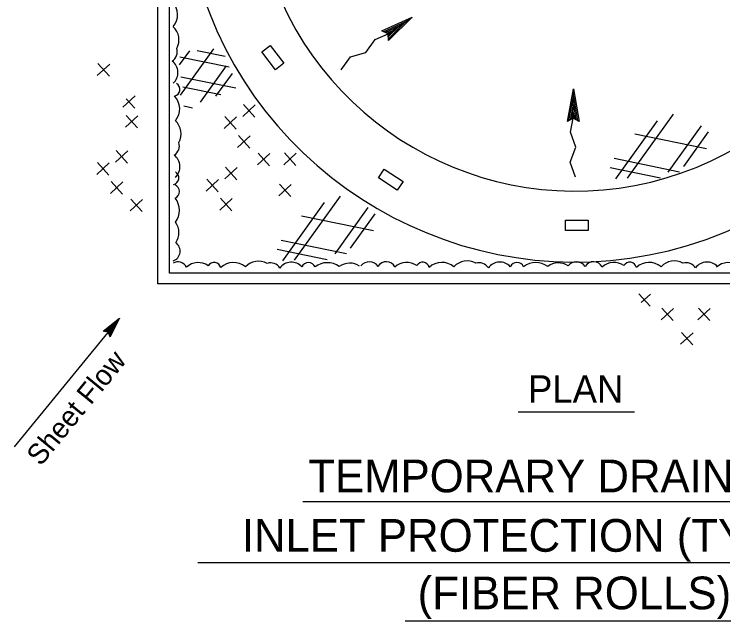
# Model space of a CAD drawing. Extents: x 6707406 to 6714471, y 1868570 to 1872341.
# Drawn here: x 6708985.5 to 6709235.1, y 1871409.4 to 1871623 of the extents above; entities that cross this region are included whole.
import ezdxf

# ---------------------------------------------------------------- set-up
doc = ezdxf.new("R2010")
doc.units = 0
for name, color, linetype in [('1 Control', 7, 'Continuous'), ('57 Undefined', 7, 'Continuous'), ('60 Nongeo Data', 7, 'Continuous'), ('62 As-Built Chng', 7, 'Continuous'), ('63 Undefined', 7, 'Continuous')]:
    doc.layers.add(name, color=color, linetype=linetype)

msp = doc.modelspace()

# ---------------------------------------------------------------- linework, layer by layer
at = {"layer": '1 Control'}
for p, q in [((6709022.59, 1871515.93), (6709022.59, 1871515.93)), ((6709016.78, 1871511.38), (6709016.78, 1871511.38)), ((6709019.26, 1871509.35), (6709019.26, 1871509.35))]:
    msp.add_line(p, q, dxfattribs=at)
msp.add_lwpolyline([(6709016.78, 1871511.38), (6709022.59, 1871515.93), (6709019.26, 1871509.35), (6709019.09, 1871509.82), (6709021.53, 1871514.64), (6709017.27, 1871511.31), (6709017.76, 1871511.24), (6709020.48, 1871513.37), (6709018.92, 1871510.29), (6709018.76, 1871510.76), (6709019.43, 1871512.09), (6709018.25, 1871511.16), (6709018.63, 1871511.11), (6709019.26, 1871509.35), (6709018.63, 1871511.11)], close=True, dxfattribs=at)
at = {"layer": '57 Undefined'}
for p, q in [((6709022.59, 1871515.93), (6708985.49, 1871470.65)), ((6709162.99, 1871482.99), (6709203.94, 1871482.99)), ((6709087.18, 1871451.4), (6709283.18, 1871451.4)), ((6709050.17, 1871429.96), (6709317.27, 1871429.96)), ((6709123.18, 1871409.38), (6709246.6, 1871409.38))]:
    msp.add_line(p, q, dxfattribs=at)
at = {"layer": '60 Nongeo Data'}
msp.add_arc((6709182.99, 1871674.08), 113.4, 20.4401, 11.3417, dxfattribs=at)
at = {"layer": '62 As-Built Chng'}
for p, q in [((6709014.75, 1871601.4), (6709019.15, 1871605.42)), ((6709015, 1871605.55), (6709019.02, 1871601.15)), ((6709023.72, 1871590.17), (6709028.12, 1871594.19)), ((6709024.99, 1871593.2), (6709027.99, 1871589.92)), ((6709065.99, 1871587), (6709070.39, 1871591.02)), ((6709066.24, 1871591.15), (6709070.26, 1871586.75)), ((6709024.9, 1871587.34), (6709028.92, 1871582.95)), ((6709024.65, 1871583.2), (6709029.05, 1871587.22)), ((6709059.42, 1871582.75), (6709063.81, 1871586.77)), ((6709059.66, 1871586.89), (6709063.68, 1871582.49)), ((6709064.21, 1871576.07), (6709068.6, 1871580.09)), ((6709064.46, 1871580.21), (6709068.48, 1871575.81)), ((6709021.17, 1871570.82), (6709025.57, 1871574.84)), ((6709021.42, 1871574.96), (6709025.44, 1871570.56)), ((6709071.17, 1871569.88), (6709075.57, 1871573.9)), ((6709071.42, 1871574.02), (6709075.44, 1871569.62)), ((6709080.45, 1871569.96), (6709084.85, 1871573.98)), ((6709080.7, 1871574.1), (6709084.72, 1871569.71)), ((6709014.6, 1871566.56), (6709019, 1871570.58)), ((6709014.85, 1871570.71), (6709018.87, 1871566.31)), ((6709059.69, 1871564.94), (6709064.09, 1871568.96)), ((6709059.94, 1871569.09), (6709063.96, 1871564.69)), ((6709053.36, 1871564.83), (6709057.38, 1871560.44)), ((6709019.39, 1871559.88), (6709023.79, 1871563.9)), ((6709019.64, 1871564.03), (6709023.66, 1871559.63)), ((6709053.12, 1871560.69), (6709057.51, 1871564.71)), ((6709078.67, 1871559.02), (6709083.07, 1871563.04)), ((6709078.92, 1871563.17), (6709082.94, 1871558.77)), ((6709026.35, 1871553.69), (6709030.75, 1871557.71)), ((6709026.6, 1871557.84), (6709030.62, 1871553.44)), ((6709057.91, 1871554.01), (6709062.3, 1871558.03)), ((6709058.16, 1871558.15), (6709062.18, 1871553.75)), ((6709205.5, 1871524.54), (6709209.52, 1871520.14)), ((6709206.37, 1871521.42), (6709209.65, 1871524.42)), ((6709213.37, 1871515.37), (6709217.77, 1871519.39)), ((6709213.62, 1871519.51), (6709217.64, 1871515.11)), ((6709226.25, 1871515.34), (6709230.64, 1871519.36)), ((6709226.5, 1871519.48), (6709230.52, 1871515.08)), ((6709220.24, 1871506.77), (6709224.64, 1871510.79)), ((6709220.49, 1871510.92), (6709224.51, 1871506.52))]:
    msp.add_line(p, q, dxfattribs=at)
for points in [[(6709036.13, 1871820.42), (6709330.46, 1871820.42), (6709330.46, 1871528.03), (6709036.13, 1871528.03)], [(6709040.24, 1871816.63), (6709326.68, 1871816.63), (6709326.68, 1871531.81), (6709040.24, 1871531.81)], [(6709072.73, 1871609.72), (6709075.65, 1871611.98), (6709080.51, 1871605.69), (6709077.59, 1871603.43)], [(6709113.77, 1871565.29), (6709115.79, 1871568.38), (6709122.45, 1871564.04), (6709120.43, 1871560.95)], [(6709179.72, 1871546.79), (6709179.72, 1871550.48), (6709187.67, 1871550.48), (6709187.67, 1871546.79)]]:
    msp.add_lwpolyline(points, close=True, dxfattribs=at)
msp.add_arc((6709182.99, 1871674.08), 138.36, 19.738, 11.782, dxfattribs=at)
at = {"layer": '63 Undefined'}
for p, q in [((6709115.05, 1871617.05), (6709125.68, 1871621.97)), ((6709115.61, 1871616.79), (6709123.42, 1871620.4)), ((6709123.42, 1871620.4), (6709117.32, 1871614.33)), ((6709125.68, 1871621.97), (6709117.37, 1871613.71)), ((6709116.19, 1871616.53), (6709121.17, 1871618.83)), ((6709116.76, 1871616.26), (6709118.87, 1871617.23)), ((6709118.87, 1871617.23), (6709117.22, 1871615.59)), ((6709121.17, 1871618.83), (6709117.27, 1871614.96)), ((6709117.18, 1871616.06), (6709115.05, 1871617.05)), ((6709117.37, 1871613.71), (6709117.18, 1871616.06)), ((6709047.22, 1871610.09), (6709043.64, 1871605.09)), ((6709055.66, 1871610.81), (6709043.95, 1871594.47)), ((6709050, 1871610.21), (6709059.82, 1871608.2)), ((6709043.85, 1871608), (6709061.24, 1871604.43)), ((6709060.14, 1871604.81), (6709050.97, 1871592.02)), ((6709044.25, 1871600.95), (6709063.58, 1871596.99)), ((6709062.25, 1871602.13), (6709056.46, 1871594.05)), ((6709044.95, 1871597.38), (6709058.33, 1871594.63)), ((6709180.37, 1871585.17), (6709182.5, 1871596.69)), ((6709182.5, 1871596.69), (6709184.44, 1871585.13)), ((6709180.91, 1871585.48), (6709182.48, 1871593.93)), ((6709182.48, 1871593.93), (6709183.91, 1871585.45)), ((6709045.24, 1871590.68), (6709048.35, 1871590.04)), ((6709181.46, 1871585.79), (6709182.46, 1871591.19)), ((6709182.46, 1871591.19), (6709183.36, 1871585.78)), ((6709182.01, 1871586.1), (6709182.43, 1871588.39)), ((6709182.43, 1871588.39), (6709182.82, 1871586.1)), ((6709217.62, 1871587.74), (6709201.45, 1871565.18)), ((6709182.42, 1871586.33), (6709180.37, 1871585.17)), ((6709184.44, 1871585.13), (6709182.42, 1871586.33)), ((6709211.99, 1871585.44), (6709197.33, 1871564.98)), ((6709227.44, 1871583.68), (6709215.74, 1871567.37)), ((6709204.09, 1871580.81), (6709229.38, 1871575.62)), ((6709229.91, 1871581.51), (6709221.23, 1871569.39)), ((6709196.84, 1871572.23), (6709219.85, 1871567.51)), ((6709195.45, 1871569.01), (6709213.12, 1871565.39)), ((6709100.27, 1871558.95), (6709084.09, 1871536.39)), ((6709094.64, 1871556.64), (6709079.97, 1871536.18)), ((6709110.08, 1871554.89), (6709098.38, 1871538.58)), ((6709112.56, 1871552.71), (6709103.87, 1871540.6)), ((6709086.73, 1871552.02), (6709112.02, 1871546.83)), ((6709079.48, 1871543.43), (6709102.5, 1871538.71)), ((6709078.1, 1871540.22), (6709095.76, 1871536.59))]:
    msp.add_line(p, q, dxfattribs=at)
for points in [[(6709100.67, 1871603.42), (6709103.92, 1871608), (6709109.35, 1871609.45), (6709112.6, 1871614.03), (6709117.18, 1871616.06), (6709125.68, 1871621.97)], [(6709183.2, 1871565.55), (6709181.34, 1871570.85), (6709183.28, 1871576.12), (6709181.42, 1871581.42), (6709182.42, 1871586.33), (6709182.5, 1871596.69)]]:
    msp.add_lwpolyline(points, dxfattribs=at)
for centre, radius, start, end in [((6709036.53, 1871622.78), 6.54, 319.9986, 43.3536), ((6709037.18, 1871613.93), 6.36, 331.3634, 46.8458), ((6709039.06, 1871609.72), 3.88, 302.3474, 17.3796), ((6709038.18, 1871602.41), 5, 312.1292, 53.705), ((6709041.42, 1871596.47), 2.4, 284.0578, 59.3233), ((6709037.25, 1871589.65), 6.54, 319.9986, 43.3536), ((6709037.91, 1871580.81), 6.36, 331.3634, 46.8458), ((6709039.79, 1871576.6), 3.88, 302.3474, 17.3796), ((6709038.9, 1871569.29), 5, 312.1292, 53.705), ((6709041.06, 1871565.34), 2.4, 284.0578, 59.3233), ((6709041.14, 1871560.52), 2.57, 294.5196, 65.4804), ((6709036.69, 1871553.87), 7, 323.3979, 37.9353), ((6709037.34, 1871546), 6.2, 325.656, 36.6973), ((6709040.26, 1871539.55), 3.68, 290.3255, 53.3403), ((6709043.13, 1871532.33), 3.41, 27.0211, 119.7865), ((6709050.32, 1871529.41), 6.1, 54.5002, 132.8354), ((6709055.92, 1871533.15), 2.4, 14.0578, 149.3233), ((6709062.74, 1871528.98), 6.54, 49.9986, 133.3536), ((6709071.58, 1871529.64), 6.36, 61.3634, 136.8458), ((6709075.79, 1871531.52), 3.88, 32.3474, 107.3796), ((6709083.1, 1871530.63), 5, 42.1292, 143.705), ((6709089.16, 1871532.92), 2.57, 24.5196, 155.4804), ((6709095.8, 1871528.47), 7, 53.3979, 127.9353), ((6709103.68, 1871529.12), 6.2, 55.656, 126.6973), ((6709110.58, 1871532.11), 3.68, 33.6905, 143.3403), ((6709116.57, 1871532.41), 3.41, 27.0211, 149.1913), ((6709123.75, 1871529.48), 6.1, 54.5002, 132.8354), ((6709129.36, 1871533.23), 2.4, 14.0578, 149.3233), ((6709136.17, 1871529.05), 6.54, 49.9986, 133.3536), ((6709145.02, 1871529.71), 6.36, 61.3634, 136.8458), ((6709149.23, 1871531.59), 3.88, 32.3474, 107.3796), ((6709156.54, 1871530.71), 5, 42.1292, 143.705), ((6709162.59, 1871532.99), 2.57, 24.5196, 155.4804), ((6709169.24, 1871528.54), 7, 53.3979, 127.9353), ((6709177.12, 1871529.19), 6.2, 55.656, 126.6973), ((6709183.56, 1871532.11), 3.68, 33.6905, 143.3403), ((6709189.55, 1871532.41), 3.41, 27.0211, 149.1913), ((6709196.74, 1871529.48), 6.1, 54.5002, 132.8354), ((6709202.34, 1871533.23), 2.4, 14.0578, 149.3233), ((6709209.16, 1871529.05), 6.54, 49.9986, 133.3536), ((6709218, 1871529.71), 6.36, 61.3634, 136.8458), ((6709222.21, 1871531.59), 3.88, 32.3474, 107.3796), ((6709229.52, 1871530.71), 5, 42.1292, 143.705), ((6709237.04, 1871529.41), 6.1, 54.5002, 132.8354)]:
    msp.add_arc(centre, radius, start, end, dxfattribs=at)

# ---------------------------------------------------------------- texts
at = {"layer": '57 Undefined'}
msp.add_text('Sheet Flow', height=7.2, rotation=50.6735, dxfattribs=at).set_placement((6708994.83, 1871463.55))
for s, height, p in [('PLAN', 9.6, (6709166.51, 1871486.21)), ('TEMPORARY DRAINAGE', 11.5197, (6709089.06, 1871454.62)), ('INLET PROTECTION (TYPE 4A)', 11.5197, (6709065.67, 1871433.7)), ('(FIBER ROLLS)', 11.5197, (6709127.61, 1871413.44))]:
    msp.add_text(s, height=height, dxfattribs=at).set_placement(p)

doc.saveas('drawing.dxf')
